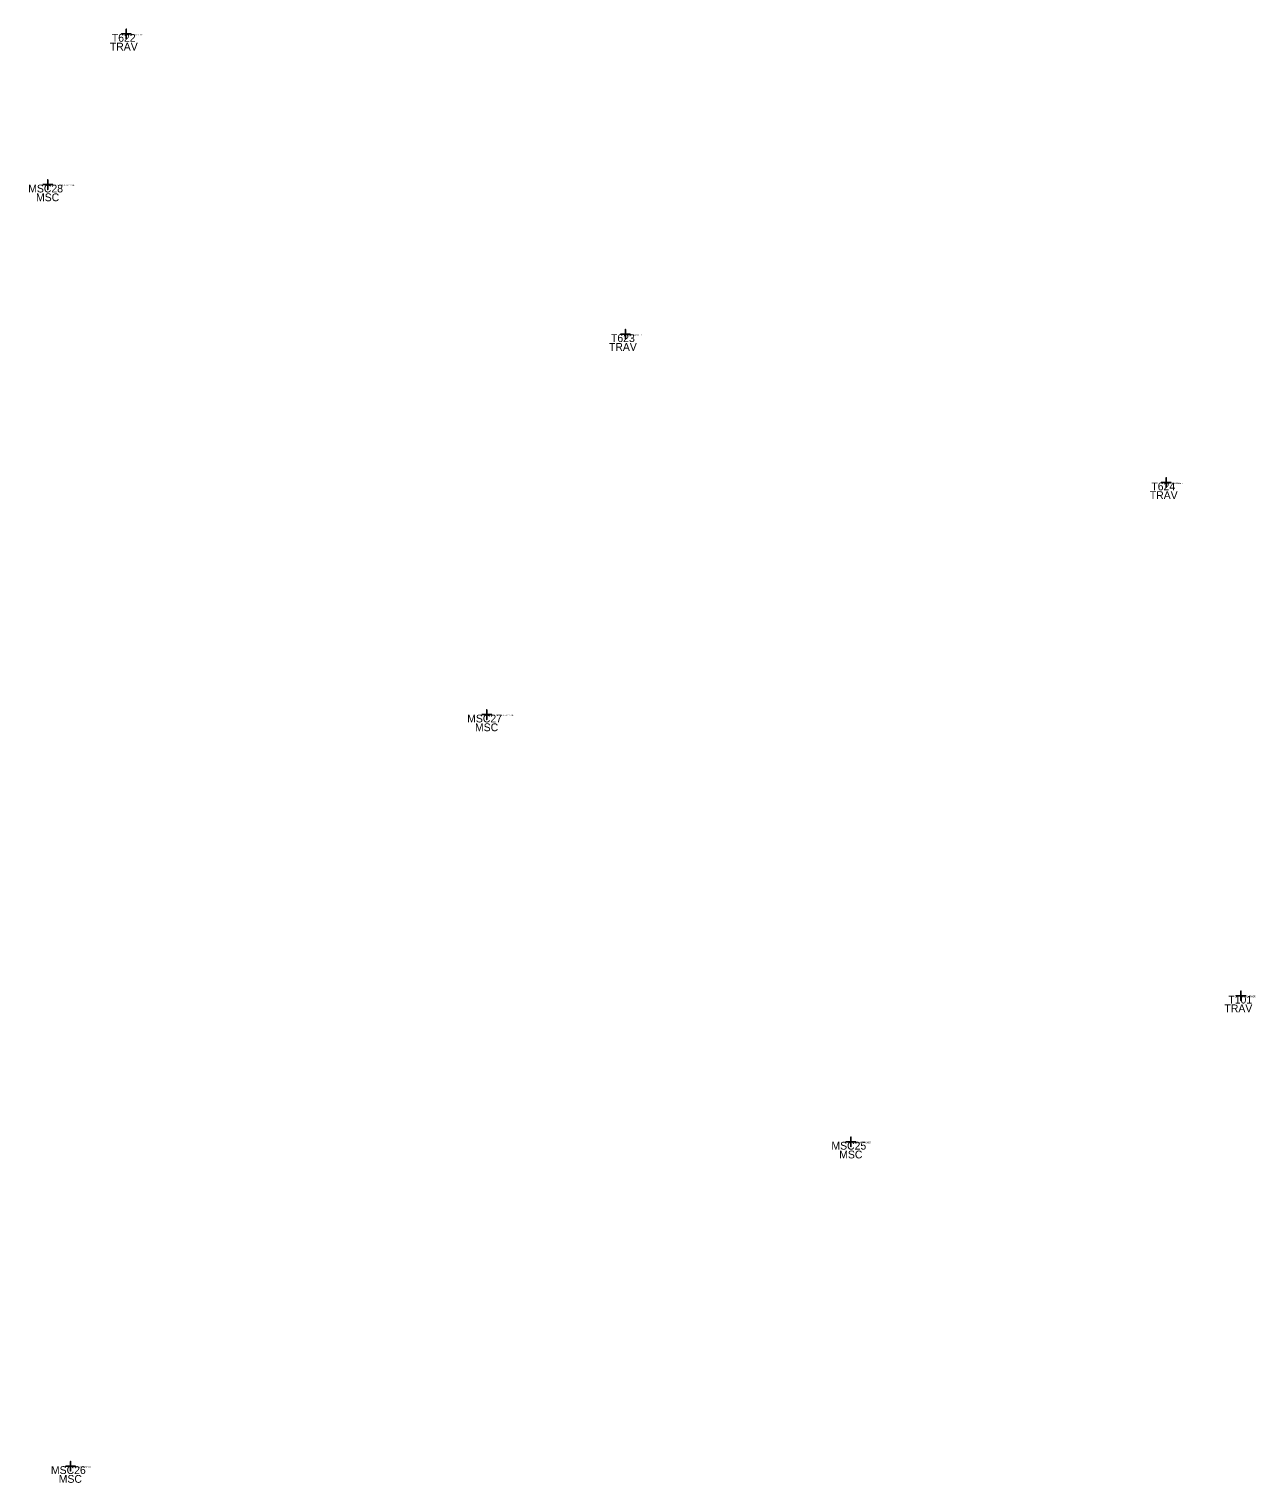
# Model space of a CAD drawing. Extents: x 2342247 to 2353588, y 365809 to 372747.
# Drawn here: x 2348059 to 2349316, y 367509 to 369000 of the extents above; entities that cross this region are included whole.
import ezdxf

# ---------------------------------------------------------------- set-up
doc = ezdxf.new("R2010")
doc.units = 0
for name, color, linetype in [('Level 63', 7, 'Continuous'), ('SV_Control_CP_Code', 7, 'Continuous'), ('SV_Control_CP_Name', 7, 'Continuous'), ('SV_Control_CP_Shot', 7, 'Continuous')]:
    doc.layers.add(name, color=color, linetype=linetype)

msp = doc.modelspace()

# ---------------------------------------------------------------- linework, layer by layer
at = {"layer": 'SV_Control_CP_Shot'}
for points in [[(2348159, 368995), (2348159, 369000), (2348159, 368995), (2348154, 368995), (2348159, 368995), (2348159, 368990), (2348159, 368995), (2348164, 368995)], [(2348078.6, 368840.5), (2348078.6, 368845.5), (2348078.6, 368840.5), (2348073.6, 368840.5), (2348078.6, 368840.5), (2348078.6, 368835.5), (2348078.6, 368840.5), (2348083.6, 368840.5)], [(2348670.6, 368687.1), (2348670.6, 368692.1), (2348670.6, 368687.1), (2348665.6, 368687.1), (2348670.6, 368687.1), (2348670.6, 368682.1), (2348670.6, 368687.1), (2348675.6, 368687.1)], [(2349224.8, 368535.1), (2349224.8, 368540.1), (2349224.8, 368535.1), (2349219.8, 368535.1), (2349224.8, 368535.1), (2349224.8, 368530.1), (2349224.8, 368535.1), (2349229.8, 368535.1)], [(2348528.5, 368297.1), (2348528.5, 368302.1), (2348528.5, 368297.1), (2348523.5, 368297.1), (2348528.5, 368297.1), (2348528.5, 368292.1), (2348528.5, 368297.1), (2348533.5, 368297.1)], [(2349301.3, 368008.9), (2349301.3, 368013.9), (2349301.3, 368008.9), (2349296.3, 368008.9), (2349301.3, 368008.9), (2349301.3, 368003.9), (2349301.3, 368008.9), (2349306.3, 368008.9)], [(2348901.7, 367859.1), (2348901.7, 367864.1), (2348901.7, 367859.1), (2348896.7, 367859.1), (2348901.7, 367859.1), (2348901.7, 367854.1), (2348901.7, 367859.1), (2348906.7, 367859.1)], [(2348101.9, 367526.5), (2348101.9, 367531.5), (2348101.9, 367526.5), (2348096.9, 367526.5), (2348101.9, 367526.5), (2348101.9, 367521.5), (2348101.9, 367526.5), (2348106.9, 367526.5)]]:
    msp.add_lwpolyline(points, close=True, dxfattribs=at)

# ---------------------------------------------------------------- texts
at = {"layer": 'Level 63'}
for s, p in [('NAIL W/WASHER', (2348159, 368993.5)), ('#5 REBAR W/ PLASTIC CAP', (2348078.6, 368839)), ('NAIL W/WASHER', (2348670.6, 368685.6)), ('NAIL W/WASHER', (2349224.8, 368533.6)), ('#5 REBAR W/ PLASTIC CAP', (2348528.5, 368295.6)), ('PK W/WASHER', (2349301.3, 368007.4)), ('PK NAIL W/ WASHER', (2348901.7, 367857.6)), ('PK NAIL W/ WASHER', (2348101.9, 367525))]:
    msp.add_text(s, height=1.5, dxfattribs=at).set_placement(p)
at = {"layer": 'SV_Control_CP_Code'}
for s, p in [('TRAV', (2348142.2, 368978)), ('MSC', (2348066.5, 368823.5)), ('TRAV', (2348653.7, 368670.1)), ('TRAV', (2349208, 368518.1)), ('MSC', (2348516.4, 368280.1)), ('TRAV', (2349284.5, 367991.9)), ('MSC', (2348889.7, 367842.1)), ('MSC', (2348089.8, 367509.5))]:
    msp.add_text(s, height=8, dxfattribs=at).set_placement(p)
at = {"layer": 'SV_Control_CP_Name'}
for s, p in [('T622', (2348144.2, 368987)), ('MSC28', (2348058.5, 368832.5)), ('T623', (2348655.8, 368679.1)), ('T624', (2349209.6, 368527.1)), ('MSC27', (2348508.4, 368289.1)), ('T101', (2349288.5, 368000.9)), ('MSC25', (2348881.7, 367851.1)), ('MSC26', (2348081.8, 367518.5))]:
    msp.add_text(s, height=8, dxfattribs=at).set_placement(p)

doc.saveas('drawing.dxf')
